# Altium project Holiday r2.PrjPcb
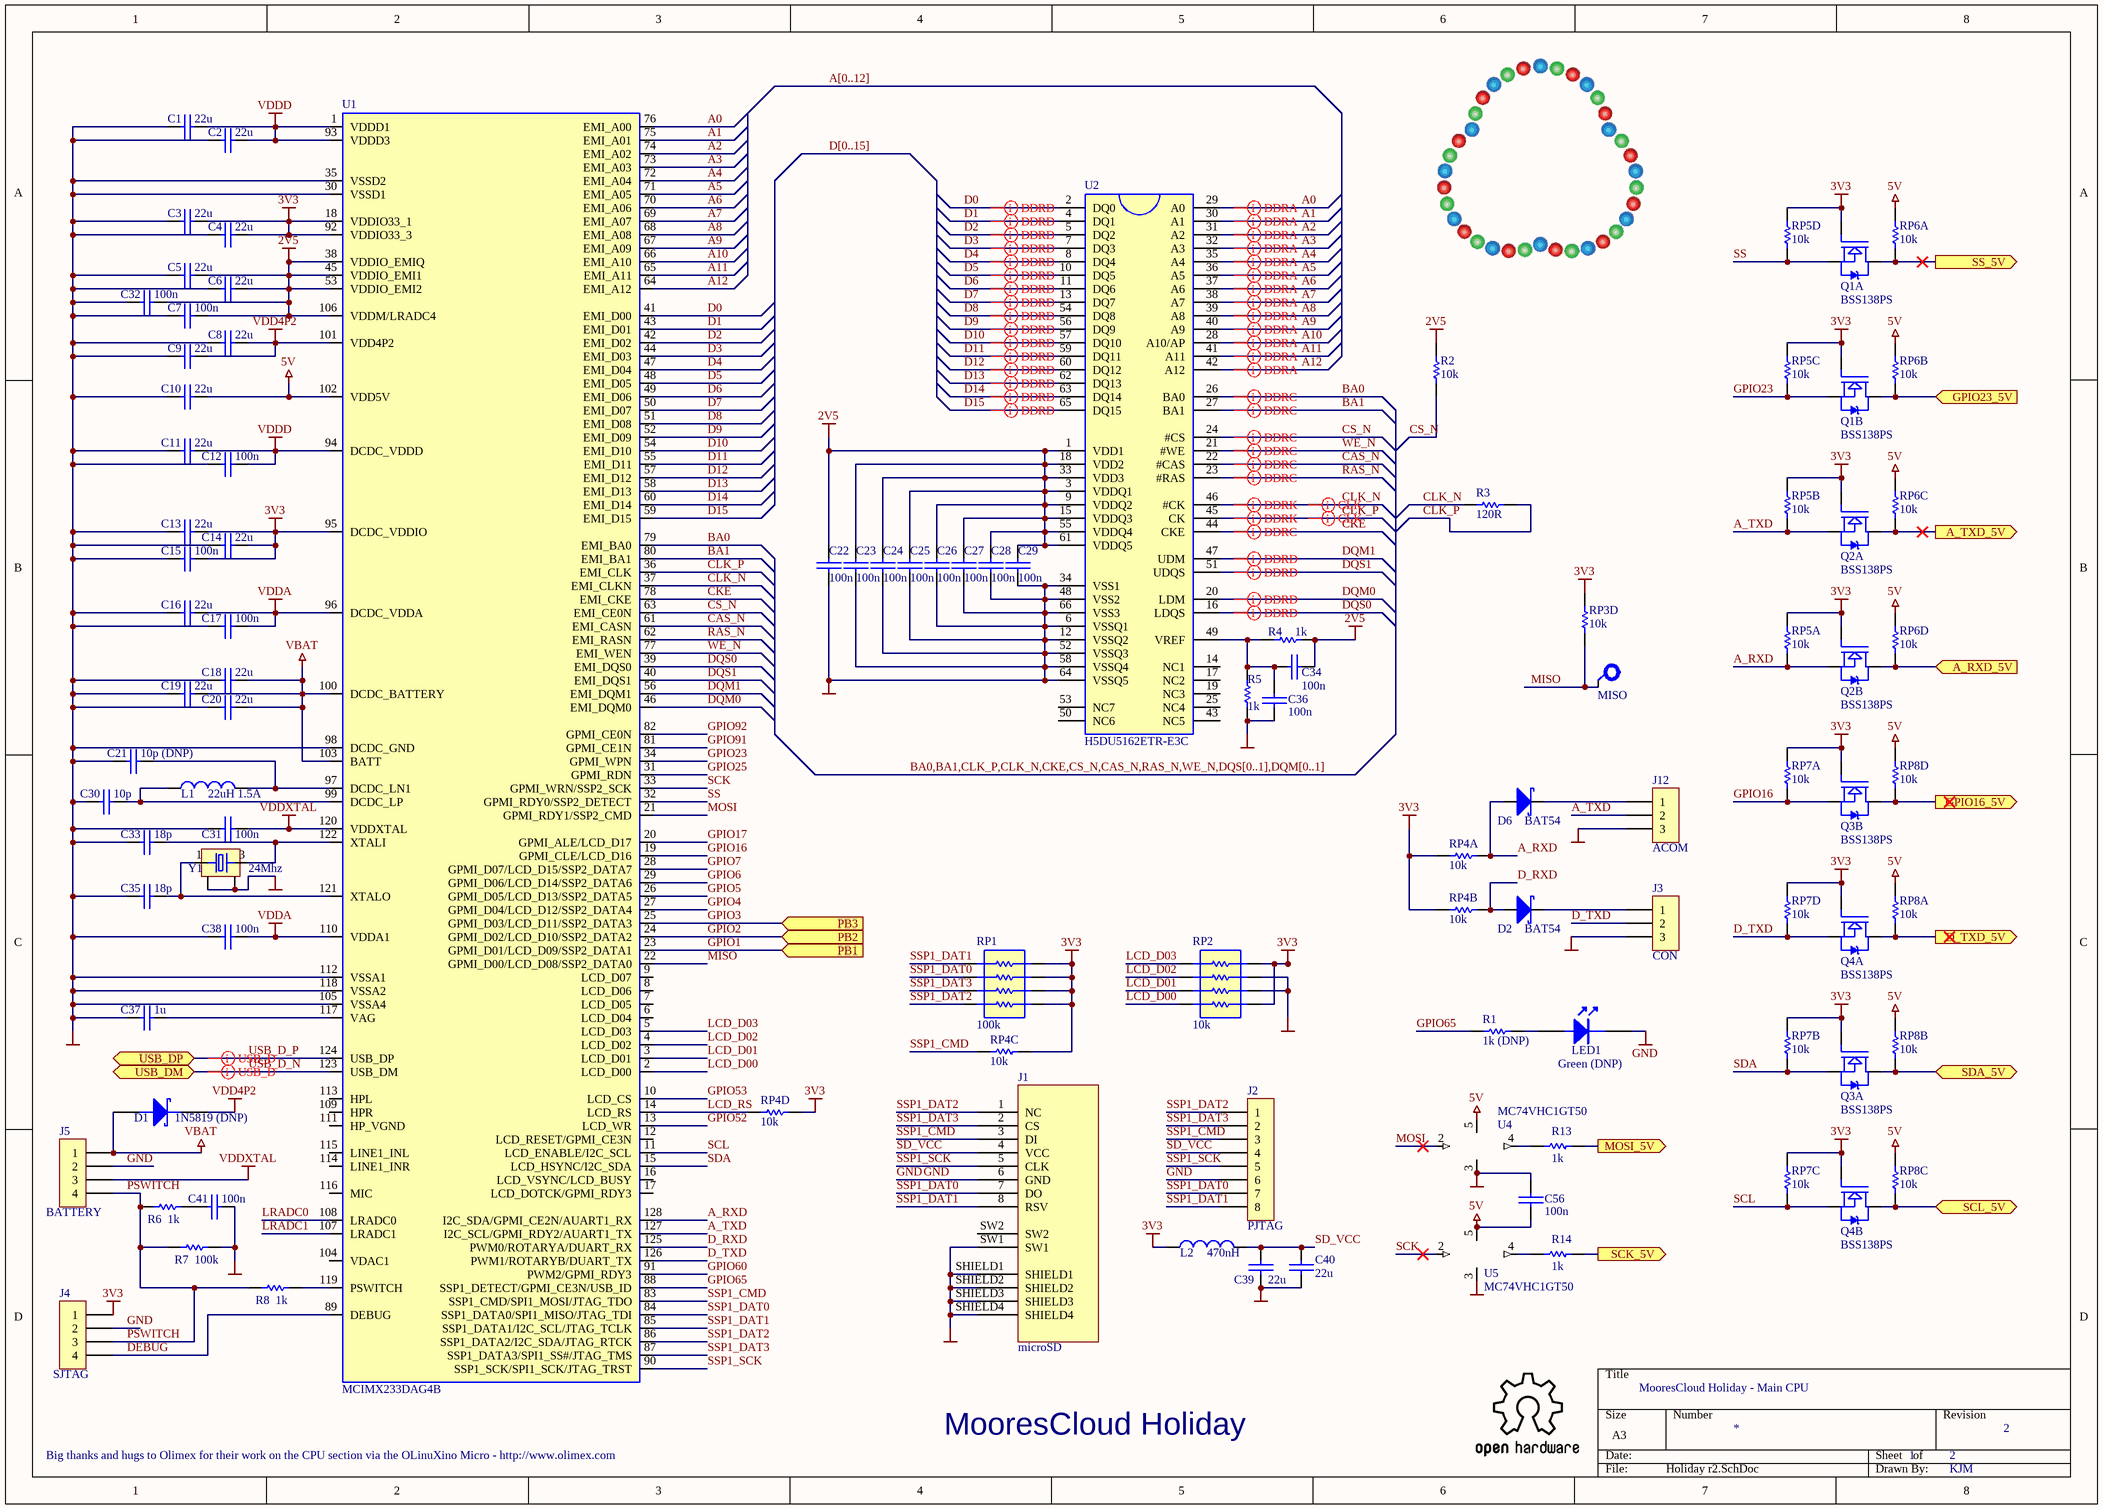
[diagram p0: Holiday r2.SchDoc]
2 sheets, 132 parts. Net scope: flat (ports and power ports of the same name join across sheets).
Board files: Holiday r2.PcbDoc, Holiday r2 Panel 2x2 (no embed).PcbDoc, Holiday r2 Panel 2x2.PcbDoc
Sheets:
  Holiday r2.SchDoc
  Holiday Aux r2.SchDoc

## Sheet Holiday r2.SchDoc: MooresCloud Holiday - Main CPU
size A3; DrawnBy: KJM; Organization: Kean Electronics for MooresCloud; Revision: 2; SheetNumber: 1; SheetTotal: 2

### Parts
C1  22u  [ARA_0603]
C2  22u  [ARA_0603]
C3  22u  [ARA_0603]
C4  22u  [ARA_0603]
C5  22u  [ARA_0603]
C6  22u  [ARA_0603]
C7  100n  [ARA_0603]
C8  22u  [ARA_0603]
C9  22u  [ARA_0603]
C10  22u  [ARA_0603]
C11  22u  [ARA_0603]
C12  100n  [ARA_0603]
C13  22u  [ARA_0603]
C14  22u  [ARA_0603]
C15  100n  [ARA_0603]
C16  22u  [ARA_0603]
C17  100n  [ARA_0603]
C18  22u  [ARA_0603]
C19  22u  [ARA_0603]
C20  22u  [ARA_0603]
C21  10p (DNP)  [ARA_0603]
C22  100n  [ARA_0603]
C23  100n  [ARA_0603]
C24  100n  [ARA_0603]
C25  100n  [ARA_0603]
C26  100n  [ARA_0603]
C27  100n  [ARA_0603]
C28  100n  [ARA_0603]
C29  100n  [ARA_0603]
C30  10p  [ARA_0603]
C31  100n  [ARA_0603]
C32  100n  [ARA_0603]
C33  18p  [ARA_0603]
C34  100n  [ARA_0603]
C35  18p  [ARA_0603]
C36  100n  [ARA_0603]
C37  1u  [ARA_0603]
C38  100n  [ARA_0603]
C39  22u  [ARA_0603]
C40  22u  [ARA_0603]
C41  100n  [ARA_0603]
C56  100n  [ARA_0603]
D1  1N5819 (DNP)  [SOD-123]
D2  BAT54  [ARA_SOT-23]
D6  BAT54  [ARA_SOT-23]
J1  microSD  [MICROSD-47309-3751 WITH CARD]
J2  PJTAG  [53047-08]  (no BOM)
J3  CON  [HDR1X3]  (no BOM)
J4  SJTAG  [HDR1X4]  (no BOM)
J5  BATTERY  [HDR1X4]  (no BOM)
J12  ACOM  [HDR1X3]  (no BOM)
L1  22uH 1.5A  [RCL_L7078]
L2  470nH  [ARA_0805]
LED1  Green (DNP)  [LED_0805]
Q1  BSS138PS  [ARA_SOT-363]  (parts A,B of 2)
Q2  BSS138PS  [ARA_SOT-363]  (parts A,B of 2)
Q3  BSS138PS  [ARA_SOT-363]  (parts A,B of 2)
Q4  BSS138PS  [ARA_SOT-363]  (parts A,B of 2)
R1  1k (DNP)  [ARA_0603]
R2  10k  [ARA_0603]
R3  120R  [ARA_0603]
R4  1k  [ARA_0603]
R5  1k  [ARA_0603]
R6  1k  [ARA_0603]
R7  100k  [ARA_0603]
R8  1k  [ARA_0603]
R13  1k  [ARA_0603]
R14  1k  [ARA_0603]
RP1  100k  [RESPACK_0603x4]
RP2  10k  [RESPACK_0603x4]
RP3  10k  [RESPACK_0603x4]  (part D of 4)
RP4  10k  [RESPACK_0603x4]  (parts A,B,C,D of 4)
RP5  10k  [RESPACK_0603x4]  (parts A,B,C,D of 4)
RP6  10k  [RESPACK_0603x4]  (parts A,B,C,D of 4)
RP7  10k  [RESPACK_0603x4]  (parts A,B,C,D of 4)
RP8  10k  [RESPACK_0603x4]  (parts A,B,C,D of 4)
TP1  MISO  [SMD_TESTTERMINAL]  (no BOM)
U1  MCIMX233DAG4B  [LQFP128]
U2  H5DU5162ETR-E3C  [TSOP-II-66]
U4  MC74VHC1GT50  [ARA_SOT-23-5L]
U5  MC74VHC1GT50  [ARA_SOT-23-5L]
Y1  24Mhz  [CRYSTAL_ABMM2]

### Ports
A_RXD_5V (in), A_TXD_5V (out), D_TXD_5V (out), GPIO16_5V (out), GPIO23_5V (in), MOSI_5V (out), PB1 (in), PB2 (in), PB3 (in), SCK_5V (out), SCL_5V (bidir), SDA_5V (bidir), SS_5V (out), USB_DM (bidir), USB_DP (bidir)

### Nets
2V5: C5.1 C6.1 C7.1 C22.1 C23.1 C24.1 C25.1 C26.1 C27.1 C28.1 C29.1 C32.1 C34.1 R2.2 R4.2 U1.38(VDDIO_EMIQ) U1.45(VDDIO_EMI1) U1.53(VDDIO_EMI2) U1.106(VDDM/LRADC4) U2.1(VDD1) U2.3(VDDQ1) U2.9(VDDQ2) U2.15(VDDQ3) U2.18(VDD2) U2.33(VDD3) U2.55(VDDQ4) U2.61(VDDQ5)
3V3: C3.1 C4.1 C13.1 C14.1 C15.1 J4.1 L2.2 Q1.2(G1) Q1.5(G2) Q2.2(G1) Q2.5(G2) Q3.2(G1) Q3.5(G2) Q4.2(G1) Q4.5(G2) RP1.1.2 RP1.2.2 RP1.3.2 RP1.4.2 RP2.1.2 RP2.4.2 RP3.4.2 RP4.1.2 RP4.2.2 RP4.3.2 RP4.4.2 RP5.1.2 RP5.2.2 RP5.3.2 RP5.4.2 RP7.1.2 RP7.2.2 RP7.3.2 RP7.4.2 U1.18(VDDIO33_1) U1.92(VDDIO33_3) U1.95(DCDC_VDDIO)
5V: C10.1 C56.2 RP6.1.2 RP6.2.2 RP6.3.2 RP6.4.2 RP8.1.2 RP8.2.2 RP8.3.2 RP8.4.2 U1.102(VDD5V) U4.5(VCC) U5.5(VCC)
GND: C1.2 C2.2 C3.2 C4.2 C5.2 C6.2 C7.2 C8.2 C9.2 C10.2 C11.2 C12.2 C13.2 C14.2 C15.2 C16.2 C17.2 C18.2 C19.2 C20.2 C21.2 C22.2 C23.2 C24.2 C25.2 C26.2 C27.2 C28.2 C29.2 C30.2 C31.2 C32.2 C33.2 C35.2 C36.2 C37.2 C38.2 C39.2 C40.2 C41.2 C56.1 J1.6(GND) J1.SHIELD1 J1.SHIELD2 J1.SHIELD3 J1.SHIELD4 J1.SW1 J2.6 J3.3 J4.2 J5.2 J12.3 LED1.K R5.2 R7.1 RP2.2.2 RP2.3.2 U1.30(VSSD1) U1.35(VSSD2) U1.98(DCDC_GND) U1.105(VSSA4) U1.112(VSSA1) U1.118(VSSA2) U2.6(VSSQ1) U2.12(VSSQ2) U2.34(VSS1) U2.48(VSS2) U2.52(VSSQ3) U2.58(VSSQ4) U2.64(VSSQ5) U2.66(VSS3) U4.3(GND) U5.3(GND) Y1.2 Y1.4
VBAT: C18.1 C19.1 C20.1 D1.1(A) J5.1 U1.100(DCDC_BATTERY) U1.103(BATT)
VDD4P2: C8.1 C9.1 D1.2(K) U1.101(VDD4P2)
VDDA: C16.1 C17.1 C38.1 U1.96(DCDC_VDDA) U1.110(VDDA1)
VDDD: C1.1 C2.1 C11.1 C12.1 U1.1(VDDD1) U1.93(VDDD3) U1.94(DCDC_VDDD)
VDDXTAL: C31.1 J5.3 U1.120(VDDXTAL)
A0: U1.76(EMI_A00) U2.29(A0)
A1: U1.75(EMI_A01) U2.30(A1)
A2: U1.74(EMI_A02) U2.31(A2)
A3: U1.73(EMI_A03) U2.32(A3)
A4: U1.72(EMI_A04) U2.35(A4)
A5: U1.71(EMI_A05) U2.36(A5)
A6: U1.70(EMI_A06) U2.37(A6)
A7: U1.69(EMI_A07) U2.38(A7)
A8: U1.68(EMI_A08) U2.39(A8)
A9: U1.67(EMI_A09) U2.40(A9)
A10: U1.66(EMI_A10) U2.28(A10/AP)
A11: U1.65(EMI_A11) U2.41(A11)
A12: U1.64(EMI_A12) U2.42(A12)
A_RXD: D6.1(A) Q2.4(S2) RP4.1.1 RP5.1.1 U1.128(I2C_SDA/GPMI_CE2N/AUART1_RX)
A_RXD_5V: Q2.3(D2) RP6.4.1 ; port A_RXD_5V
A_TXD: J12.2 Q2.1(S1) RP5.2.1 U1.127(I2C_SCL/GPMI_RDY2/AUART1_TX)
A_TXD_5V: Q2.6(D1) RP6.3.1 ; port A_TXD_5V
BA0: U1.79(EMI_BA0) U2.26(BA0)
BA1: U1.80(EMI_BA1) U2.27(BA1)
CAS_N: U1.61(EMI_CASN) U2.22(#CAS)
CKE: U1.78(EMI_CKE) U2.44(CKE)
CLK_N: R3.1 U1.37(EMI_CLKN) U2.46(#CK)
CLK_P: R3.2 U1.36(EMI_CLK) U2.45(CK)
CS_N: R2.1 U1.63(EMI_CE0N) U2.24(#CS)
D0: U1.41(EMI_D00) U2.2(DQ0)
D1: U1.43(EMI_D01) U2.4(DQ1)
D2: U1.42(EMI_D02) U2.5(DQ2)
D3: U1.44(EMI_D03) U2.7(DQ3)
D4: U1.47(EMI_D04) U2.8(DQ4)
D5: U1.48(EMI_D05) U2.10(DQ5)
D6: U1.49(EMI_D06) U2.11(DQ6)
D7: U1.50(EMI_D07) U2.13(DQ7)
D8: U1.51(EMI_D08) U2.54(DQ8)
D9: U1.52(EMI_D09) U2.56(DQ9)
D10: U1.54(EMI_D10) U2.57(DQ10)
D11: U1.55(EMI_D11) U2.59(DQ11)
D12: U1.57(EMI_D12) U2.60(DQ12)
D13: U1.58(EMI_D13) U2.62(DQ13)
D14: U1.60(EMI_D14) U2.63(DQ14)
D15: U1.59(EMI_D15) U2.65(DQ15)
D_RXD: D2.1(A) RP4.2.1 U1.125(PWM0/ROTARYA/DUART_RX)
D_TXD: J3.2 Q4.1(S1) RP7.4.1 U1.126(PWM1/ROTARYB/DUART_TX)
D_TXD_5V: Q4.6(D1) RP8.1.1 ; port D_TXD_5V
DEBUG: J4.4 U1.89(DEBUG)
DQM0: U1.46(EMI_DQM0) U2.20(LDM)
DQM1: U1.56(EMI_DQM1) U2.47(UDM)
DQS0: U1.39(EMI_DQS0) U2.16(LDQS)
DQS1: U1.40(EMI_DQS1) U2.51(UDQS)
GPIO1: U1.23(GPMI_D01/LCD_D09/SSP2_DATA1) ; port PB1
GPIO2: U1.24(GPMI_D02/LCD_D10/SSP2_DATA2) ; port PB2
GPIO3: U1.25(GPMI_D03/LCD_D11/SSP2_DATA3) ; port PB3
GPIO4: U1.27(GPMI_D04/LCD_D12/SSP2_DATA4)
GPIO5: U1.26(GPMI_D05/LCD_D13/SSP2_DATA5)
GPIO6: U1.29(GPMI_D06/LCD_D14/SSP2_DATA6)
GPIO7: U1.28(GPMI_D07/LCD_D15/SSP2_DATA7)
GPIO16: Q3.4(S2) RP7.1.1 U1.19(GPMI_CLE/LCD_D16)
GPIO17: U1.20(GPMI_ALE/LCD_D17)
GPIO23: Q1.4(S2) RP5.3.1 U1.34(GPMI_WPN)
GPIO23_5V: Q1.3(D2) RP6.2.1 ; port GPIO23_5V
GPIO25: U1.31(GPMI_RDN)
GPIO52: U1.13(LCD_WR)
GPIO53: U1.10(LCD_CS)
GPIO60: U1.91(PWM2/GPMI_RDY3)
GPIO65: R1.2 U1.88(SSP1_DETECT/GPMI_CE3N/USB_ID)
GPIO91: U1.81(GPMI_CE1N)
GPIO92: U1.82(GPMI_CE0N)
LCD_D00: RP2.4.1 U1.2(LCD_D00)
LCD_D01: RP2.3.1 U1.3(LCD_D01)
LCD_D02: RP2.2.1 U1.4(LCD_D02)
LCD_D03: RP2.1.1 U1.5(LCD_D03)
LCD_RS: RP4.4.1 U1.14(LCD_RS)
LRADC0: U1.108(LRADC0)
LRADC1: U1.107(LRADC1)
MISO: RP3.4.1 TP1.1 U1.22(GPMI_D00/LCD_D08/SSP2_DATA0)
MOSI: U1.21(GPMI_RDY1/SSP2_CMD) U4.2(IN)
MOSI_5V: R13.1 ; port MOSI_5V
PSWITCH: J4.3 J5.4 R6.2 R7.2 R8.2
RAS_N: U1.62(EMI_RASN) U2.23(#RAS)
RESET_N: Q3.3(D2) RP8.4.1 ; port GPIO16_5V
SCK: U1.33(GPMI_WRN/SSP2_SCK) U5.2(IN)
SCK_5V: R14.1 ; port SCK_5V
SCL: Q4.4(S2) RP7.3.1 U1.11(LCD_ENABLE/I2C_SCL)
SCL_5V: Q4.3(D2) RP8.3.1 ; port SCL_5V
SD_VCC: C39.1 C40.1 J1.4(VCC) J2.4 L2.1
SDA: Q3.1(S1) RP7.2.1 U1.15(LCD_HSYNC/I2C_SDA)
SDA_5V: Q3.6(D1) RP8.2.1 ; port SDA_5V
SS: Q1.1(S1) RP5.4.1 U1.32(GPMI_RDY0/SSP2_DETECT)
SS_5V: Q1.6(D1) RP6.1.1 ; port SS_5V
SSP1_CMD: J1.3(DI) J2.3 RP4.3.1 U1.83(SSP1_CMD/SPI1_MOSI/JTAG_TDO)
SSP1_DAT0: J1.7(DO) J2.7 RP1.2.1 U1.84(SSP1_DATA0/SPI1_MISO/JTAG_TDI)
SSP1_DAT1: J1.8(RSV) J2.8 RP1.1.1 U1.85(SSP1_DATA1/I2C_SCL/JTAG_TCLK)
SSP1_DAT2: J1.1(NC) J2.1 RP1.4.1 U1.86(SSP1_DATA2/I2C_SDA/JTAG_RTCK)
SSP1_DAT3: J1.2(CS) J2.2 RP1.3.1 U1.87(SSP1_DATA3/SPI1_SS#/JTAG_TMS)
SSP1_SCK: J1.5(CLK) J2.5 U1.90(SSP1_SCK/SPI1_SCK/JTAG_TRST)
USB_D_N: U1.123(USB_DM) ; port USB_DM
USB_D_P: U1.124(USB_DP) ; port USB_DP
WE_N: U1.77(EMI_WEN) U2.21(#WE)
NetC21_1: C21.1 L1.1 U1.97(DCDC_LN1)
NetC30_1: C30.1 L1.2 U1.99(DCDC_LP)
NetC33_1: C33.1 U1.122(XTALI) Y1.3
NetC34_2: C34.2 C36.1 R4.1 R5.1 U2.49(VREF)
NetC35_1: C35.1 U1.121(XTALO) Y1.1
NetC37_1: C37.1 U1.117(VAG)
NetC41_1: C41.1 R6.1
NetD2_2: D2.2(K) J3.1
NetD6_2: D6.2(K) J12.1
NetLED1_A: LED1.A R1.1
NetR8_1: R8.1 U1.119(PSWITCH)
NetR13_2: R13.2 U4.4(OUT)
NetR14_2: R14.2 U5.4(OUT)

Not connected (* = marked no-connect by the designer): J1 SW2; U1 6(LCD_D04) 7(LCD_D05) 8(LCD_D06) 9(LCD_D07) 12(LCD_RESET/GPMI_CE3N) 16(LCD_VSYNC/LCD_BUSY) 17(LCD_DOTCK/GPMI_RDY3) 104(VDAC1) 109(HPR) 111(HP_VGND) 113(HPL) 114(LINE1_INR) 115(LINE1_INL) 116(MIC); U2 14(NC1) 17(NC2) 19(NC3) 25(NC4) 43(NC5) 50(NC6) 53(NC7); U4 1; U5 1

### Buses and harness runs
bus A[0..12]
bus BA0,BA1,CLK_P,CLK_N,CKE,CS_N,CAS_N,RAS_N,WE_N,DQS[0..1],DQM[0..1]
bus D[0..15]

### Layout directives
net class DDR_DATA: D0, D1, D2, D3, D4, D5, D6, D7, D8, D9, D10, D11, D12, D13, D14, D15, DQM0, DQM1, DQS0, DQS1
net class DDR_ADDR: A0, A1, A2, A3, A4, A5, A6, A7, A8, A9, A10, A11, A12
net class DDR_CLK: CLK_N, CLK_P
differential pair: CLK_N, CLK_P, USB_D_N, USB_D_P
net class DDR_CTL: BA0, BA1, CAS_N, CKE, CS_N, RAS_N, WE_N

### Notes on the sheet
- Big thanks and hugs to Olimex for their work on the CPU section via the OLinuXino Micro - http://www.olimex.com
- MooresCloud Holiday

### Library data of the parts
C1-C6 C8-C11 C13 C14 C16 C18-C20 C39 C40 = CAP: Capacitor; 1.Manufacturer: TDK; 2.MfgNo: C1608X5R0J226M080AC; 4.CatNo: 445-8028-1-ND; 9.UnitCost: 0.0816
C7 C12 C15 C17 C22-C29 C31 C32 C34 C36 C38 C41 C56 = CAP: Capacitor; 1.Manufacturer: Yageo; 4.CatNo: 311-1343-2-ND; 2.MfgNo: CC0603ZRY5V9BB104; 9.UnitCost: 0.0034
C21 C30 = CAP: Capacitor; 1.Manufacturer: Murata; 4.CatNo: 490-1403-1-ND; 2.MfgNo: GRM1885C1H100JA01D; 9.UnitCost: 0.008
C33 C35 = CAP: Capacitor; 1.Manufacturer: Murata; 2.MfgNo: GRM1885C1H180JA01D; 4.CatNo: 490-1409-2-ND; 9.UnitCost: 0.008
C37 = CAP: Capacitor; 1.Manufacturer: Yageo; 4.CatNo: 311-1372-2-ND; 2.MfgNo: CC0603ZRY5V7BB105; 9.UnitCost: 0.0083
D1 = DIODE SCHOTTKY: Schottky Diode 1N5819HW (DNP); 1.Manufacturer: Diodes Inc; 2.MfgNo: 1N5819HW-7-F; 4.CatNo: 1N5819HW-FDITR-ND; 9.UnitCost: 0.08
D2 D6 = BAT54: Schottky Diode; pin to pad: 2>3; 1.Manufacturer: Fairchild; 4.CatNo: BAT54FSTR-ND; 9.UnitCost: 0.027
J1 = microSD: microSD Socket Push/Pull; pin to pad: SHIELD1>G1 SHIELD2>G1 SHIELD3>G2 SHIELD4>G2 SW1>G3 SW2>G4; 1.Manufacturer: Molex; 2.MfgNo: 473093751; 4.CatNo: WM3974TR-ND; 9.UnitCost: 0.90
J2 = CON8: Connector; 1.Manufacturer: DNP; 9.UnitCost: 0
J3 J12 = CON3: Connector; 1.Manufacturer: DNP; 9.UnitCost: 0
J4 J5 = CON4: Connector; 1.Manufacturer: DNP; 9.UnitCost: 0
L1 = Inductor: 1.Manufacturer: Taiyo Yuden; 2.MfgNo: NR6045T220M; 4.CatNo: 587-2082-1-ND; 9.UnitCost: 0.12
L2 = Inductor: Ferrite; 1.Manufacturer: Abracon; 2.MfgNo: AISC-0805-R47J-T; 4.CatNo: 535-10509-1-ND; 9.UnitCost: 0.10
LED1 = LED: 1.Manufacturer: Kingbright; 4.CatNo: 754-1131-1-ND; 9.UnitCost: 0.0611; 2.MfgNo: APT2012SGC
Q1-Q4 = BSS138PS: Dual N Channel MOSFET; 1.Manufacturer: NXP; 4.CatNo: 568-8393-2-ND; 2.MfgNo: BSS138PS,115; 9.UnitCost: 0.07
R1 R4-R6 R8 R13 R14 = Res Semi: Resistor; 1.Manufacturer: Yageo; 4.CatNo: 311-1.00KHRTR-ND; 2.MfgNo: RC0603FR-071KL; 9.UnitCost: 0.0017
R2 = Res Semi: Resistor; 1.Manufacturer: Yageo; 9.UnitCost: 0.0017; 4.CatNo: 311-10.0KHRTR-ND; 2.MfgNo: RC0603FR-0710KL
R3 = Res Semi: Resistor; 1.Manufacturer: Yageo; 4.CatNo: 311-120HRTR-ND; 2.MfgNo: RC0603FR-07120RL; 9.UnitCost: 0.0017
R7 = Res Semi: Resistor; 1.Manufacturer: Yageo; 4.CatNo: 311-100KHRTR-ND; 2.MfgNo: RC0603FR-07100KL; 9.UnitCost: 0.0017
RP1 = RESISTOR_PACK_4_1206: Resistor Pack 4x0603; 1.Manufacturer: Vishay Dale; 2.MfgNo: CRA06S083100KJTA; 4.CatNo: CRA6S8100KTR-ND; 9.UnitCost: 0.009
RP2 = RESISTOR_PACK_4_1206: Resistor Pack 4x0603; 1.Manufacturer: Vishay Dale; 2.MfgNo: CRA06S08310K0JTA; 4.CatNo: CRA6S810KTR-ND; 9.UnitCost: 0.009
RP3-RP8 = RESISTOR_PACK_4_1206_SPLIT: Resistor Pack 4x0603; 1.Manufacturer: Vishay Dale; 2.MfgNo: CRA06S08310K0JTA; 4.CatNo: CRA6S810KTR-ND; 9.UnitCost: 0.009
TP1 = TESTTERMINAL: Test Point
U1 = MCIMX233DAG4B: Freescale i.MX233 128 pin LQFP package; 2.MfgNo: MCIMX233DAG4C; 4.CatNo: MCIMX233DAG4C-ND; 9.UnitCost: 4.880
U2 = H5DU5162ETR-E3C: SDRAM DDR400 66TSOP-II; 1.Manufacturer: Hynix; 9.UnitCost: 2.240
U4 U5 = MC74VHC1GT50: CMOS Logic Level Shifter; 1.Manufacturer: On Semi; 2.MfgNo: M74VHC1GT50DTT1G; 4.CatNo: M74VHC1GT50DTT1GOSTR-ND; 9.UnitCost: 0.07
Y1 = CRYSTAL_ABMM2: ABMM2 SMD Crystal; 1.Manufacturer: Abracon; 2.MfgNo: ABMM2-24.000MHZ-E2-T; 4.CatNo: 535-9638-2-ND; 9.UnitCost: 0.48

## Sheet Holiday Aux r2.SchDoc: MooresCloud Holiday - Aux CPU & I/O
size A4; DrawnBy: KJM; Organization: Kean Electronics for MooresCloud; Revision: 2; SheetNumber: 2; SheetTotal: 2
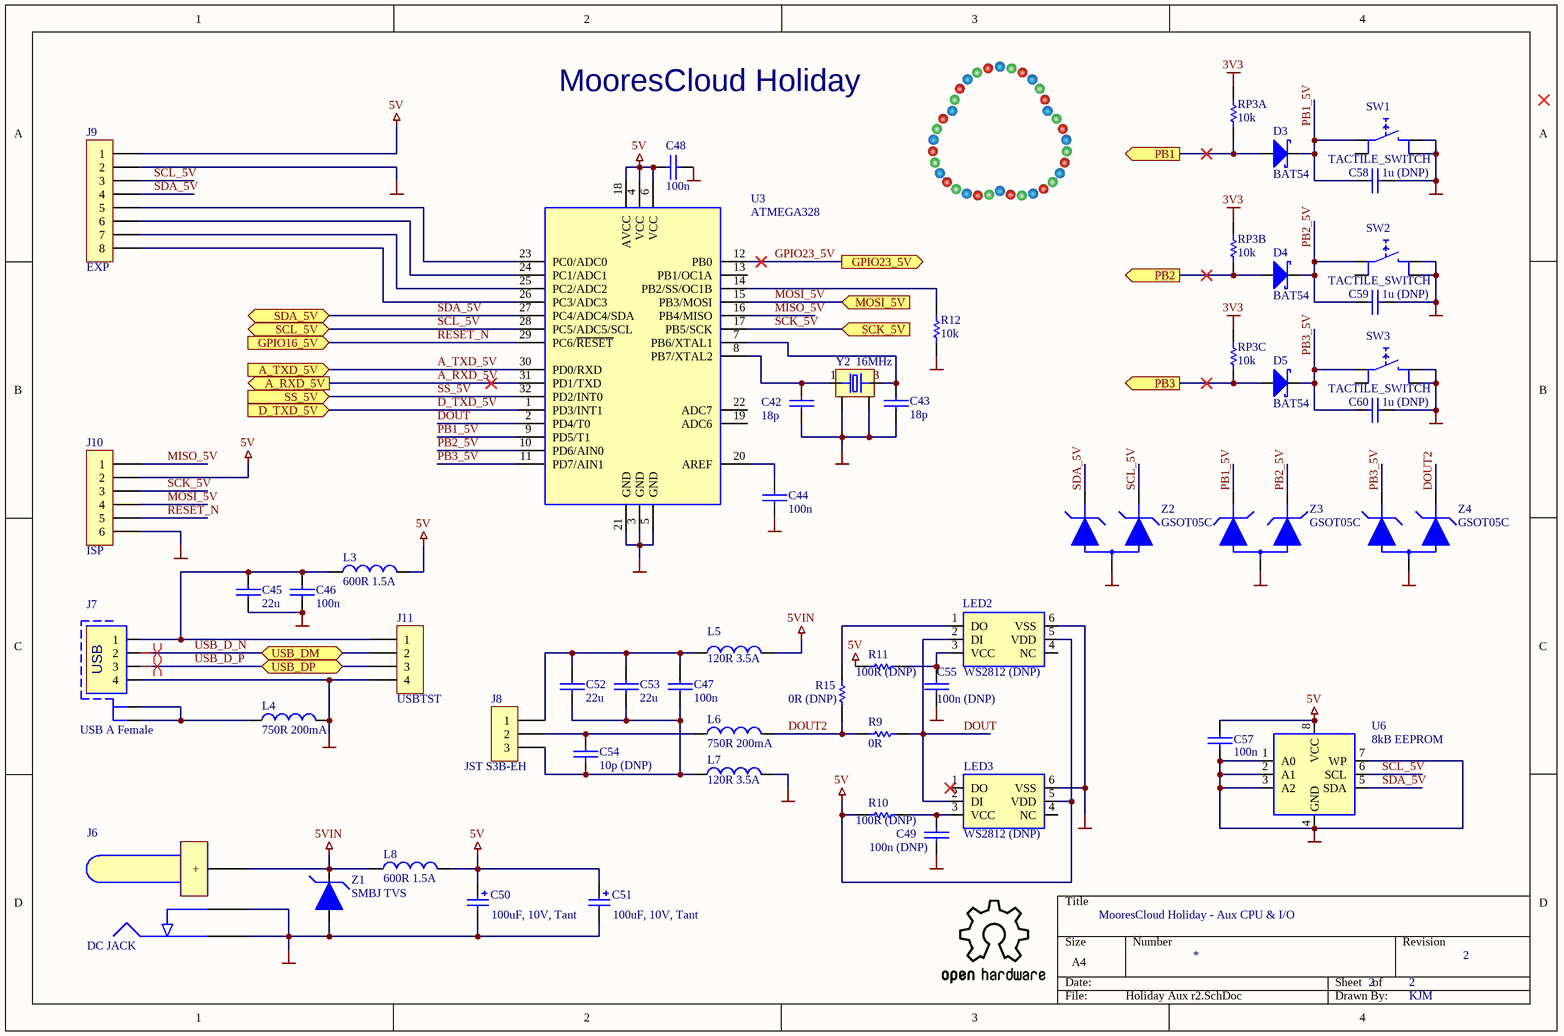
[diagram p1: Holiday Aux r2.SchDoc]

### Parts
C42  18p  [ARA_0603]
C43  18p  [ARA_0603]
C44  100n  [ARA_0603]
C45  22u  [ARA_0603]
C46  100n  [ARA_0603]
C47  100n  [ARA_0603]
C48  100n  [ARA_0603]
C49  100n (DNP)  [ARA_0603]
C50  100uF, 10V, Tant  [ARA_TAJD]
C51  100uF, 10V, Tant  [ARA_TAJD]
C52  22u  [ARA_0603]
C53  22u  [ARA_0603]
C54  10p (DNP)  [ARA_0603]
C55  100n (DNP)  [ARA_0603]
C57  100n  [ARA_0603]
C58  1u (DNP)  [ARA_0603]
C59  1u (DNP)  [ARA_0603]
C60  1u (DNP)  [ARA_0603]
D3  BAT54  [ARA_SOT-23]
D4  BAT54  [ARA_SOT-23]
D5  BAT54  [ARA_SOT-23]
J6  DC JACK  [PJ-002AH-SMT]
J7  USB A Female  [USB-A-FEMALE-SMT NANO WIFI]
J8  JST S3B-EH  [JST-EH-S3B WITH PLUG]
J9  EXP  [HDR1X8]  (no BOM)
J10  ISP  [HDR2x3]  (no BOM)
J11  USBTST  [HDR1X4]  (no BOM)
L3  600R 1.5A  [ARA_0805]
L4  750R 200mA  [ARA_0603]
L5  120R 3.5A  [ARA_0805]
L6  750R 200mA  [ARA_0603]
L7  120R 3.5A  [ARA_0805]
L8  600R 1.5A  [ARA_0805]
LED2  WS2812 (DNP)  [PLCC6-IPC]
LED3  WS2812 (DNP)  [PLCC6-IPC]
R9  0R  [ARA_0603]
R10  100R (DNP)  [ARA_0603]
R11  100R (DNP)  [ARA_0603]
R12  10k  [ARA_0603]
R15  0R (DNP)  [ARA_0603]
RP3  10k  [RESPACK_0603x4]  (parts A,B,C of 4)
SW1  TACTILE_SWITCH  [TACTILE_SWITCH_SMD]
SW2  TACTILE_SWITCH  [TACTILE_SWITCH_SMD]
SW3  TACTILE_SWITCH  [TACTILE_SWITCH_SMD]
U3  ATMEGA328  [TQFP32]
U6  8kB EEPROM  [SO-8]
Y2  16MHz  [CRYSTAL_ABMM2]
Z1  SMBJ TVS  [ARA_DO-214AC]
Z2  GSOT05C  [ARA_SOT-23]
Z3  GSOT05C  [ARA_SOT-23]
Z4  GSOT05C  [ARA_SOT-23]

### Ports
A_RXD_5V (out), A_TXD_5V (in), D_TXD_5V (in), GPIO16_5V (in), GPIO23_5V (out), MOSI_5V (in), PB1 (out), PB2 (out), PB3 (out), SCK_5V (in), SCL_5V (bidir), SDA_5V (bidir), SS_5V (in), USB_DM (bidir), USB_DP (bidir)

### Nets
3V3: RP3.1.2 RP3.2.2 RP3.3.2
5V: C48.1 C50.1 C51.1 C57.1 J9.1 J10.2 L3.1 L8.1 LED2.5(VDD) LED3.5(VDD) R10.2 R11.2 U3.4(VCC) U3.6(VCC) U3.18(AVCC) U6.8(VCC)
5VIN: J6.1(+) L5.1 L8.2 Z1.2(K)
GND: C42.2 C43.2 C44.2 C45.2 C46.2 C48.2 C49.1 C50.2 C51.2 C55.1 C57.2 C58.1 C59.1 C60.1 J6.2 J6.3 J7.4 J9.2 J10.6 J11.4 L4.1 L7.1 LED2.6(VSS) LED3.6(VSS) R12.1 SW1.3 SW1.4 SW2.3 SW2.4 SW3.3 SW3.4 U3.3(GND) U3.5(GND) U3.21(GND) U6.1(A0) U6.2(A1) U6.3(A2) U6.4(GND) U6.7(WP) Y2.2 Y2.4 Z1.1(A) Z2.3 Z3.3 Z4.3
A_RXD_5V: U3.31(PD1/TXD) ; port A_RXD_5V
A_TXD_5V: U3.30(PD0/RXD) ; port A_TXD_5V
D_TXD_5V: U3.1(PD3/INT1) ; port D_TXD_5V
DOUT: LED2.2(DI) LED3.2(DI) R9.2 U3.2(PD4/T0)
DOUT2: L6.1 R9.1 R15.1 Z4.2
GPIO1: D3.1(A) RP3.1.1 ; port PB1
GPIO2: D4.1(A) RP3.2.1 ; port PB2
GPIO3: D5.1(A) RP3.3.1 ; port PB3
GPIO23_5V: U3.12(PB0) ; port GPIO23_5V
MISO_5V: J10.1 U3.16(PB4/MISO)
MOSI_5V: J10.4 U3.15(PB3/MOSI) ; port MOSI_5V
PB1_5V: C58.2 D3.2(K) SW1.1 U3.9(PD5/T1) Z3.2
PB2_5V: C59.2 D4.2(K) SW2.1 U3.10(PD6/AIN0) Z3.1
PB3_5V: C60.2 D5.2(K) SW3.1 U3.11(PD7/AIN1) Z4.1
RESET_N: J10.5 U3.29(PC6/~{RESET}) ; port GPIO16_5V
SCK_5V: J10.3 U3.17(PB5/SCK) ; port SCK_5V
SCL_5V: J9.3 U3.28(PC5/ADC5/SCL) U6.6(SCL) Z2.2 ; port SCL_5V
SDA_5V: J9.4 U3.27(PC4/ADC4/SDA) U6.5(SDA) Z2.1 ; port SDA_5V
SS_5V: U3.32(PD2/INT0) ; port SS_5V
USB_D_N: J7.2 J11.2 ; port USB_DM
USB_D_P: J7.3 J11.3 ; port USB_DP
NetC42_1: C42.1 U3.8(PB7/XTAL2) Y2.1
NetC43_1: C43.1 U3.7(PB6/XTAL1) Y2.3
NetC44_1: C44.1 U3.20(AREF)
NetC45_1: C45.1 C46.1 J7.1 J11.1 L3.2
NetC47_1: C47.1 C52.2 C53.2 C54.1 J8.3 L7.2
NetC47_2: C47.2 C52.1 C53.1 J8.1 L5.2
NetC49_2: C49.2 LED3.3(VCC) R10.1
NetC54_2: C54.2 J8.2 L6.2
NetC55_2: C55.2 LED2.3(VCC) R11.1
NetJ7_G1: J7.G1 J7.G2 L4.2
NetJ9_5: J9.5 U3.23(PC0/ADC0)
NetJ9_6: J9.6 U3.24(PC1/ADC1)
NetJ9_7: J9.7 U3.25(PC2/ADC2)
NetJ9_8: J9.8 U3.26(PC3/ADC3)
NetLED2_1: LED2.1(DO) R15.2
NetR12_2: R12.2 U3.14(PB2/SS/OC1B)

Not connected (* = marked no-connect by the designer): LED2 4(NC); LED3 1(DO)* 4(NC); SW1 2; SW2 2; SW3 2; U3 13(PB1/OC1A) 19(ADC6) 22(ADC7)

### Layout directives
differential pair: USB_D_N, USB_D_P

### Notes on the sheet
- MooresCloud Holiday

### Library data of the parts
C42 C43 = CAP: as C33 on sheet Holiday r2
C44 C46-C49 C55 C57 = CAP: as C7 on sheet Holiday r2
C45 C52 C53 = CAP: as C1 on sheet Holiday r2
C50 C51 = Cap Pol3: Polarized Capacitor (Surface Mount); 1.Manufacturer: AVX; 2.MfgNo: TPSD107K010R0100; 4.CatNo: 478-1777-2-ND; 9.UnitCost: 0.33
C54 = CAP: as C21 on sheet Holiday r2
C58-C60 = CAP: as C37 on sheet Holiday r2
D3-D5 = BAT54: Schottky Diode; pin to pad: 2>3; 1.Manufacturer: Fairchild; 4.CatNo: BAT54FSTR-ND; 9.UnitCost: 0.027
J6 = DCJACK: 1.Manufacturer: CUI Inc; 2.MfgNo: PJ-002AH-SMT-TR; 4.CatNo: CP-002AHPJTR-ND; 9.UnitCost: 0.6554
J7 = USB_A_FEMALE: 1.Manufacturer: Assmann; 2.MfgNo: AU-Y1006-R; 4.CatNo: AE9924-ND; 9.UnitCost: 0.430
J8 = CON3: Connector; 4.CatNo: 455-1626-ND; 2.MfgNo: S3B-EH(LF)(SN); 9.UnitCost: 0.07216
J9 = CON8: as J2 on sheet Holiday r2
J10 = CON6: Connector; 1.Manufacturer: DNP; 9.UnitCost: 0
J11 = CON4: as J4 on sheet Holiday r2
L3 L8 = Inductor: Ferrite; 1.Manufacturer: Laird; 2.MfgNo: MI0805K601R-10; 4.CatNo: 240-2390-2-ND; 9.UnitCost: 0.025
L4 L6 = Inductor: Ferrite; 1.Manufacturer: Laird; 2.MfgNo: HZ0603B751R-10; 4.CatNo: 240-2547-2-ND; 9.UnitCost: 0.0165
L5 L7 = Inductor: Ferrite; 1.Manufacturer: Laird; 2.MfgNo: HI0805O121R-10; 4.CatNo: 240-2393-2-ND; 9.UnitCost: 0.0234
LED2 LED3 = WS2812: WorldSemi WS2812 Smart RGB LED; 4.CatNo: sc-WS2811-5050; 9.UnitCost: 0.15
R9 R15 = Res Semi: Resistor; 1.Manufacturer: Yageo; 4.CatNo: 311-0.0GRTR-ND; 2.MfgNo: RC0603JR-070RL; 9.UnitCost: 0.00131
R10 R11 = Res Semi: Resistor; 1.Manufacturer: Yageo; 4.CatNo: 311-100GRTR-ND; 2.MfgNo: RC0603JR-07100RL; 9.UnitCost: 0.00131
R12 = Res Semi: as R2 on sheet Holiday r2
RP3 = RESISTOR_PACK_4_1206_SPLIT: as RP3 on sheet Holiday r2
SW1-SW3 = TACTILE_SWITCH: Pushbutton SMT; 1.Manufacturer: TE Connectivity; 4.CatNo: 450-1759-2-ND; 2.MfgNo: FSM4JSMATR; 9.UnitCost: 0.1543
U3 = ATMEGA328-TQFP32: ATMEGA328 - TQFP; 1.Manufacturer: Atmel; 4.CatNo: ATMEGA328-AURTR-ND; 2.MfgNo: ATMEGA328-AUR; 9.UnitCost: 1.608
U6 = EEPROM I2C: CAT24C64W EEPROM I2C; 1.Manufacturer: On Semi; 4.CatNo: CAT24C64WI-GT3TR-ND; 2.MfgNo: CAT24C64WI-GT3; 9.UnitCost: 0.148
Y2 = CRYSTAL_ABMM2: ABMM2 SMD Crystal; 1.Manufacturer: Abracon; 2.MfgNo: ABMM2-16.000MHZ-E2-T; 4.CatNo: 535-9634-2-ND; 9.UnitCost: 0.48
Z1 = TVS SMBJ: SMBJ Unidirectional TVS; 1.Manufacturer: Bourns; 4.CatNo: SMBJ6.0ABTR-ND; 2.MfgNo: SMBJ6.0A; 9.UnitCost: 0.10
Z2-Z4 = GSOT03C: Two-Line ESD-Protection in SOT23; 1.Manufacturer: Vishay Semi; 2.MfgNo: GSOT05C-GS08; 4.CatNo: 751-1415-2-ND; 9.UnitCost: 0.085

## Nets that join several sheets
3V3: Holiday r2 (37 pins), Holiday Aux r2 (RP3.1.2 RP3.2.2 RP3.3.2)
5V: Holiday r2 (13 pins), Holiday Aux r2 (16 pins)
GND: Holiday r2 (75 pins), Holiday Aux r2 (45 pins)
A_RXD_5V: Holiday r2 (Q2.3 RP6.4.1), Holiday Aux r2 (U3.31)
A_TXD_5V: Holiday r2 (Q2.6 RP6.3.1), Holiday Aux r2 (U3.30)
D_TXD_5V: Holiday r2 (Q4.6 RP8.1.1), Holiday Aux r2 (U3.1)
GPIO1: Holiday r2 (U1.23), Holiday Aux r2 (D3.1 RP3.1.1)
GPIO2: Holiday r2 (U1.24), Holiday Aux r2 (D4.1 RP3.2.1)
GPIO3: Holiday r2 (U1.25), Holiday Aux r2 (D5.1 RP3.3.1)
GPIO23_5V: Holiday r2 (Q1.3 RP6.2.1), Holiday Aux r2 (U3.12)
MOSI_5V: Holiday r2 (R13.1), Holiday Aux r2 (J10.4 U3.15)
RESET_N: Holiday r2 (Q3.3 RP8.4.1), Holiday Aux r2 (J10.5 U3.29)
SCK_5V: Holiday r2 (R14.1), Holiday Aux r2 (J10.3 U3.17)
SCL_5V: Holiday r2 (Q4.3 RP8.3.1), Holiday Aux r2 (J9.3 U3.28 U6.6 Z2.2)
SDA_5V: Holiday r2 (Q3.6 RP8.2.1), Holiday Aux r2 (J9.4 U3.27 U6.5 Z2.1)
SS_5V: Holiday r2 (Q1.6 RP6.1.1), Holiday Aux r2 (U3.32)
USB_D_N: Holiday r2 (U1.123), Holiday Aux r2 (J7.2 J11.2)
USB_D_P: Holiday r2 (U1.124), Holiday Aux r2 (J7.3 J11.3)

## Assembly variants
Standard: not fitted C21 C49 C54 C55 C58 C59 C60 D1 D6 J2 J3 J4 J5 J9 J10 LED1 LED2 LED3 R1 R10 R11 R15
With Optional Parts: not fitted C21 C54 D1 J2 J3 J4 J5 J9 J10 R9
